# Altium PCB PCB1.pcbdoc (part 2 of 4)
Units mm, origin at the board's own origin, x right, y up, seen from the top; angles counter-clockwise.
Board outline 77.9 x 107.7 mm, 4 copper layers (Top Layer, Inner1, Inner2, Bottom Layer); 106 components, 123 nets, 650 pads, 272 vias.
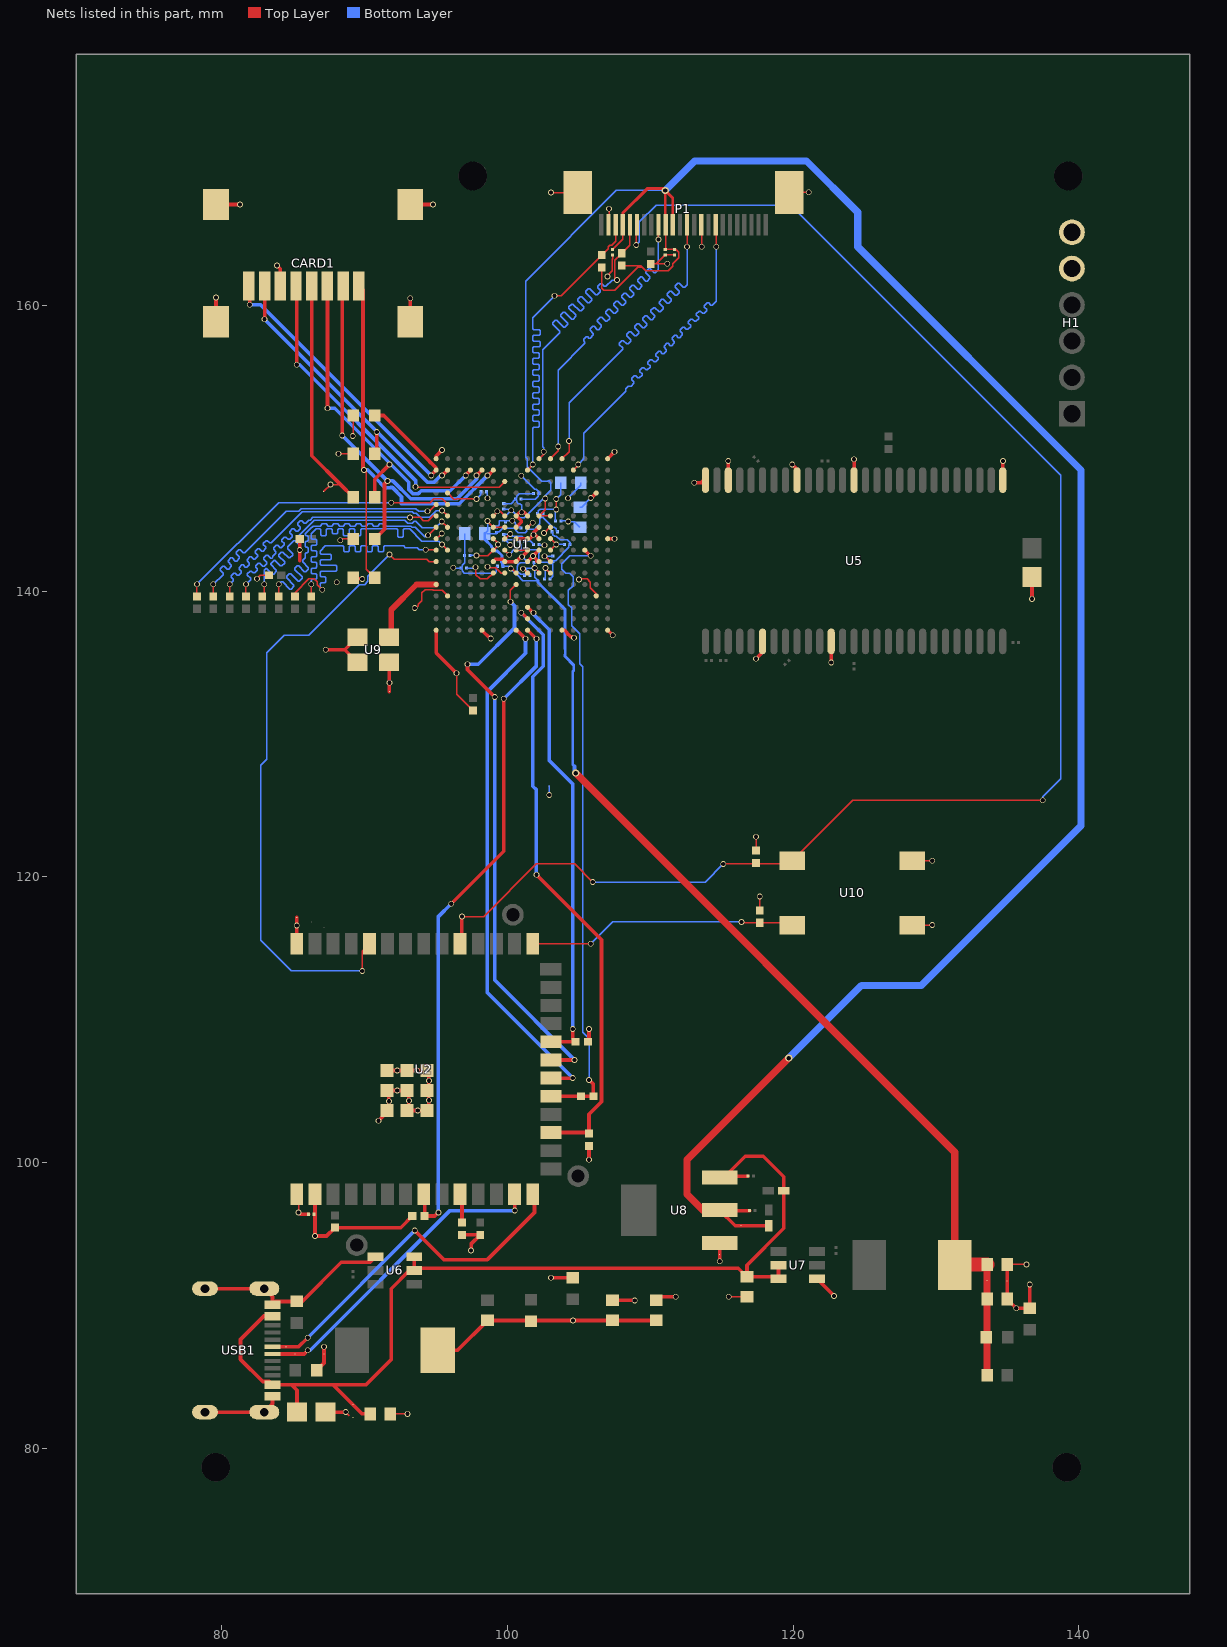
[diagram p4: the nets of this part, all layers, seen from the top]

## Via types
v1: diameter 0.4, hole 0.3, Top Layer to Bottom Layer, 269 vias
v2: diameter 0.5, hole 0.3, Top Layer to Bottom Layer, 3 vias

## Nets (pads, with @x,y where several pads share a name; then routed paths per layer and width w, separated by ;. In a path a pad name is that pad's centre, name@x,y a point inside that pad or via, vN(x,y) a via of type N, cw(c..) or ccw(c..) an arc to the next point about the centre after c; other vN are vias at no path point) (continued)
+1V1: C25.2 C27.2 C28.2 C41.1 C42.1 C43.1 C44.1 C49.1 C53.1 C54.1 C61.1 L2.2 pad.55@104.707,127.741 pad.55@133.577,91.767 R15.2 U1.G6 U1.G7 U1.L8 U1.L9 U1.L10 | length 89.6
  Top Layer w0.1: v1@98.611,144.911 98.611,144.873 U1.G6@99.024,144.46 U1.G7@99.824,144.46 ; v1(100.253,141.581) 100.303,141.581 U1.L8@100.624,141.26 ; v1(101.107,141.563) 101.121,141.563 U1.L9@101.424,141.26 ; v1(101.913,141.609) 102.224,141.298 U1.L10@102.224,141.26
  Top Layer w0.5: v2(104.79,127.258) 131.313,100.735 L2.2@131.313,92.835 ; C25.2@133.577,85.133 C28.2@133.577,90.467 pad.55@133.577,91.767 C27.2@133.577,92.88
  Top Layer w1: L2.2@131.313,92.835 131.357,92.88 C27.2@133.577,92.88
  Bottom Layer w0.1: C61.1@98.485,144.086 98.619,144.219 v1(98.619,144.903) ; C61.1@98.549,144.022 99.241,144.022 99.383,144.164 ; C41.1@99.246,144.081 99.246,144.149 99.261,144.164 99.383,144.164 ; C54.1@99.695,141.736 100.098,141.736 v1(100.253,141.581) 100.505,141.329 100.505,141.314 100.903,140.916 100.903,140.907 101.077,140.733 102.153,140.733 101.913,140.974 v1(101.913,141.609) ; C53.1@101.6,141.101 101.6,141.212 101.248,141.563 v1(101.107,141.563) 101.153,141.609 v1(101.913,141.609) ; C49.1@101.854,141.99 101.854,141.668 v1(101.913,141.609) ; C43.1@102.489,145.419 102.489,145.246 ; C44.1@103.505,144.149 103.422,144.232 103.422,144.343 103.303,144.461 103.193,144.461 102.489,145.165 102.489,145.246 ; 99.383,144.164 99.439,144.164 99.673,144.398 100.511,144.398 100.611,144.298 100.611,144.247 100.767,144.091 101.246,144.091 101.346,144.191 101.346,144.33 102.009,144.33 102.009,144.439 102.285,144.715 102.285,145.042 102.489,145.246
  Bottom Layer w0.2: C61.1@98.422,144.022 98.422,143.621 98.9,143.143 98.9,143.072 99.165,142.807 99.298,142.807 99.624,142.481 99.624,142.148 99.595,142.119 99.595,142.017 99.662,141.95 99.662,141.769 C54.1@99.695,141.736 ; 102.153,140.733 102.153,140.606 104.052,138.708 104.052,135.962 104.06,135.954 104.06,135.58 104.052,135.572 104.052,135.41 104.651,134.811 104.651,134.437 104.58,134.366 104.58,127.868 pad.55@104.707,127.741
  Bottom Layer w0.254: pad.55@104.707,127.741 104.707,127.341 v2(104.79,127.258)
+1V8: C29.1 C32.2 C34.1 C35.1 C36.1 C62.1 C63.1 P1.4 P1.10 P1.11 pad.55@116.341,95.598 R38.2 R39.2 U1.F10 U1.F11 U8.2 | length 173.3
  Top Layer w0.1: v1(102.656,146.475) 102.656,146.233 102.642,146.218 102.642,145.902 102.656,145.888 102.656,145.692 U1.F10@102.224,145.26 U1.F11@103.024,145.26 ; R38.2@106.612,162.639 106.612,162.176 106.608,162.172 106.608,161.171 106.739,161.04 107.521,161.04 109.12,162.639 109.456,162.639 ; C34.1@107.374,163.902 108.081,164.61 P1.4@108.081,165.626 ; R39.2@108.009,162.766 109.329,162.766 109.456,162.639 ; P1.10@111.081,165.626 111.081,163.927 C36.1@111.057,163.902 C35.1@111.692,163.902 111.802,163.902 112.004,163.701 112.004,163.323 111.586,162.905 111.586,162.727 111.267,162.408 109.687,162.408 109.456,162.639
  Top Layer w0.2: P1.4@108.081,165.626 108.081,166.439 109.794,168.152 110.93,168.152 v2(111.057,168.025) ; P1.10@111.081,165.626 111.057,165.651 v2(111.057,168.025) ; P1.11@111.581,165.626 111.581,167.501 v2(111.057,168.025)
  Top Layer w0.254: C29.1@116.958,96.651 114.889,96.651 115.943,95.598 pad.55@116.341,95.598 C32.2@118.296,95.598
  Top Layer w0.5: U8.2@114.861,96.68 113.695,96.68 112.581,97.794 112.581,100.207 v2(119.693,107.319)
  Bottom Layer w0.1: C63.1@99.754,145.732 100.2,145.732 v1(100.271,145.66) ; C62.1@99.881,145.233 99.881,145.269 v1(100.271,145.66) ; v2(111.057,168.025) 107.628,168.025 101.278,161.675 101.278,149.356 101.384,149.25 101.384,148.681 102.396,147.669 102.827,147.669 102.863,147.705 102.929,147.705 103.044,147.59 103.044,147.064 102.656,146.676 v1(102.656,146.475) 102.544,146.475 101.181,145.112 100.848,145.112 100.3,145.66 v1(100.271,145.66)
  Bottom Layer w0.5: v2(111.057,168.025) 113.117,170.085 120.935,170.085 124.519,166.501 124.519,164.088 140.14,148.467 140.14,123.575 128.964,112.399 124.773,112.399 v2(119.693,107.319)
+3V3: C8.2 C17.2 C19.2 C22.2 C23.2 C37.1 C39.1 C40.1 C45.1 C46.1 C47.1 C48.1 C50.1 C51.1 C52.1 C55.1 C56.1 C57.1 C58.1 C59.1 CARD1.4 H1.5 L1.2 pad.55@87.15,146.964 R3.1 R4.1 R5.2 R7.2 R11.2 R16.2 R17.2 R18.2 R19.2 R20.2 R21.2 R22.2 R23.1 U1.F6 U1.F7 U1.G9 U1.G11 U1.H6 U1.H7 U1.H11 U1.J6 U1.J7 U1.J11 U1.K11 U1.L6 U1.L7 U1.L11 U2.2 U9.1 U9.4 | length 83
  Top Layer w0.1: v1(82.484,140.858) 82.727,141.101 R23.1@83.319,141.101 ; pad.55@87.15,146.964 v1(87.637,147.451) 88.328,147.451 88.33,147.453 ; v1(88.197,149.61) R18.2@89.221,149.61 ; v1(88.324,143.556) 88.409,143.641 R17.2@89.221,143.641 ; v1@89.221,150.88 R19.2@89.221,152.277 ; v1(97.776,141.66) 97.806,141.63 97.806,141.138 98.096,140.847 98.611,140.847 U1.L6@99.024,141.26 ; v1@97.849,142.498 98.045,142.498 98.065,142.478 98.642,142.478 U1.J6@99.024,142.86 99.352,143.188 v1(99.352,143.259) 99.352,143.332 U1.H6@99.024,143.66 ; v1(98.624,141.708) 98.69,141.642 99.182,141.642 99.564,141.26 U1.L7@99.824,141.26 ; U1.F6@99.024,145.26 99.292,145.528 v1(99.292,145.578) 99.506,145.578 U1.F7@99.824,145.26 ; U1.J7@99.824,142.86 100.135,142.549 v1@100.135,142.498 ; U1.H7@99.824,143.66 99.871,143.66 v1(100.207,143.996) ; U1.G9@101.424,144.46 101.748,144.784 v1(101.786,144.784) ; v1@102.548,142.371 102.713,142.371 U1.K11@103.024,142.06 ; v1(102.576,144.06) 102.976,144.46 U1.G11@103.024,144.46 ; v1(102.675,141.609) U1.L11@103.024,141.26 ; U1.J11@103.024,142.86 103.424,143.26 v1(103.437,143.26) 103.037,143.66 U1.H11@103.024,143.66
  Top Layer w0.254: CARD1.4@86.319,161.345 86.319,149.465 88.33,147.453 R20.2@89.221,146.562 ; U2.2@86.668,97.807 86.546,97.685 v1(86.546,94.873) 87.36,94.873 R7.2@87.943,95.456 92.538,95.456 R5.2@93.352,96.27 ; v1(87.308,135.894) 88.635,135.894 ; R16.2@89.217,140.923 89.293,140.847 v1(89.848,140.847) ; U9.1@89.51,135.019 88.635,135.894 ; U9.4@89.51,136.769 88.635,135.894 ; L1.2@95.134,86.872 96.517,86.872 C19.2@98.611,88.966 101.605,88.966 R11.2@101.659,88.913 101.712,88.966 v1(104.594,88.966) C23.2@107.374,88.966 C22.2@110.422,88.966 ; R21.2@96.833,94.948 R22.2@98.103,94.948 97.468,94.313 v1(97.468,93.857) ; R3.1@105.648,108.462 105.723,108.537 v1(105.723,109.351) ; v1(105.723,100.207) R4.1@105.723,101.171 ; v1(136.711,139.45) C8.2@136.711,140.99
  Bottom Layer w0.1: C51.1@97.155,141.609 97.725,141.609 v1(97.776,141.66) ; C56.1@97.409,142.498 97.833,142.498 v1(97.841,142.49) ; C37.1@98.552,146.943 98.611,146.884 v1(98.611,146.495) ; C45.1@99.754,143.963 100.174,143.963 v1(100.207,143.996) 100.377,143.826 101.017,143.826 101.136,143.708 101.136,143.597 C46.1@101.219,143.514 101.591,143.514 C47.1@101.845,143.26 ; v1(100.135,142.539) 100.575,142.979 100.575,143.006 ; C50.1@100.965,146.435 101.964,146.435 102.152,146.622 102.152,146.733 C39.1@102.235,146.816 102.235,146.927 102.033,147.128 101.908,147.128 v1(100.976,148.06) ; v1(102.606,142.43) 103.173,142.43 C52.1@103.183,142.439 ; C48.1@102.616,140.847 102.675,140.906 v1(102.675,141.609) ; v1(103.437,143.26) C55.1@104.004,143.26 ; C40.1@103.759,144.911 104.22,144.911 v1(104.27,144.861) 104.692,144.861 C59.1@105.088,144.465 ; v1(104.248,146.483) 105.153,147.388 C58.1@105.153,147.578
  other v1: 88.07,140.607 89.188,150.847
+5V: C20.2 C26.2 C30.1 C31.2 C33.2 pad.55@89.194,83.081 U6.2 U6.3 U7.2 U7.3 U8.3 USB1.A4B9 USB1.B4A9 | length 72.1
  Top Layer w0.254: USB1.A4B9@83.574,89.272 82.977,89.272 81.339,87.634 81.339,86.238 82.884,84.693 83.353,84.693 USB1.B4A9@83.574,84.472 84.904,84.472 ; C33.2@85.292,82.554 85.292,84.084 84.904,84.472 ; C20.2@90.418,82.427 89.848,82.427 pad.55@89.194,83.081 87.803,84.472 ; U6.3@93.484,93.41 U6.2@93.484,92.46 ; U8.3@114.861,98.98 115.164,98.98 U8.3@115.248,99.064 ; C30.1@116.831,99.064 U8.3@115.248,99.064 ; U7.2@118.978,92.841 U7.3@118.978,91.891 118.852,92.017 C26.2@116.772,92.017 ; 84.904,84.472 87.803,84.472 ; 87.803,84.472 90.115,84.472 91.88,86.237 91.88,91.19 93.15,92.46 U6.2@93.484,92.46 ; U6.2@93.484,92.46 93.649,92.626 116.163,92.626 C26.2@116.772,92.017 ; U8.3@115.248,99.064 116.645,100.461 117.915,100.461 119.349,99.027 C31.2@119.349,98.048 119.349,95.407 116.772,92.83 C26.2@116.772,92.017
CCLK: R6.1 R6.2 U1.J14 U2.19 | length 44.3
  Top Layer w0.254: U2.19@103.188,104.652 R6.1@105.163,104.652 R6.2@106.029,104.652 106.029,105.489 v1(105.723,105.795) ; U1.J14@105.424,142.86 105.807,142.477 v1(105.85,142.477)
  Bottom Layer w0.1: v1(105.723,105.795) 105.723,108.674 105.269,109.128 105.269,134.697 105.067,134.899 105.067,137.001 104.51,137.557 104.51,138.813 104.282,139.042 104.282,140.041 104.601,140.36 104.601,141.014 104.365,141.249 104.08,141.249 103.795,141.533 103.795,141.901 104.371,142.477 v1(105.85,142.477)
CRYSTAL: U1.M1 U9.3 | length 5.9
  Top Layer w0.4: U9.3@91.71,136.769 91.88,136.939 91.88,138.688 93.652,140.46 U1.M1@95.024,140.46
D0: R26.1 U1.E2 | length 21
  Top Layer w0.1: R26.1@78.291,139.629 v1(78.291,140.466) ; v1@91.88,146.181 94.604,146.181 94.866,146.442 95.442,146.442 U1.E2@95.824,146.06
  Bottom Layer w0.1: v1(78.291,140.466) 84.006,146.181 v1(91.889,146.181)
D1: R27.1 U1.E1 | length 21.1
  Top Layer w0.1: R27.1@79.434,139.629 v1(79.434,140.466) ; v1(94.42,145.575) 94.539,145.575 U1.E1@95.024,146.06
  Bottom Layer w0.1: v1(79.434,140.466) 80.119,141.151 80.119,141.251 79.901,141.469 79.901,141.569 80.084,141.751 80.184,141.751 80.402,141.534 80.502,141.534 80.685,141.717 80.685,141.817 80.467,142.034 80.467,142.134 80.65,142.317 80.75,142.317 80.967,142.1 81.067,142.1 81.25,142.282 81.25,142.382 81.033,142.6 81.033,142.7 81.216,142.883 81.316,142.883 81.533,142.665 81.633,142.665 84.543,145.575 85.403,145.575 85.581,145.753 93.613,145.753 93.791,145.575 v1(94.42,145.575)
D2: R28.1 U1.F2 | length 21.5
  Top Layer w0.1: R28.1@80.577,139.629 v1(80.577,140.466) ; v1(95.433,145.63) 95.454,145.63 U1.F2@95.824,145.26
  Bottom Layer w0.1: v1(80.577,140.466) 80.831,140.72 80.831,140.82 80.677,140.974 80.677,141.074 80.86,141.257 80.96,141.257 81.114,141.103 81.214,141.103 81.396,141.286 81.396,141.386 81.242,141.54 81.242,141.64 81.425,141.823 81.525,141.823 81.679,141.669 81.779,141.669 81.962,141.851 81.962,141.951 81.808,142.105 81.808,142.205 81.991,142.388 82.091,142.388 82.245,142.234 82.345,142.234 82.528,142.417 82.528,142.517 82.374,142.671 82.374,142.771 82.557,142.954 82.657,142.954 82.811,142.8 82.911,142.8 83.094,142.983 83.094,143.083 82.94,143.237 82.94,143.337 83.122,143.52 83.222,143.52 83.376,143.366 83.476,143.366 85.664,145.553 93.361,145.553 93.471,145.444 93.639,145.444 93.91,145.173 94.586,145.173 95.043,145.63 v1(95.433,145.63)
D3: R29.1 U1.F1 | length 20.7
  Top Layer w0.1: R29.1@81.72,139.629 v1(81.72,140.466) ; v1(93.195,145.151) 93.894,145.151 94.126,144.919 94.459,144.919 94.817,145.277 95.007,145.277 U1.F1@95.024,145.26
  Bottom Layer w0.1: v1(81.72,140.466) 82.039,140.785 82.039,140.885 81.822,141.103 81.822,141.203 82.004,141.386 82.104,141.386 82.224,141.266 82.324,141.266 82.507,141.449 82.507,141.549 82.387,141.668 82.387,141.768 82.57,141.951 82.67,141.951 82.888,141.734 82.988,141.734 83.17,141.917 83.17,142.017 82.953,142.234 82.953,142.334 83.136,142.517 83.236,142.517 83.453,142.3 83.553,142.3 83.606,142.352 83.606,142.448 83.818,142.661 83.818,142.761 83.649,142.93 83.649,143.03 83.831,143.213 83.931,143.213 84.101,143.043 84.201,143.043 84.384,143.226 84.384,143.326 84.214,143.496 84.214,143.596 84.397,143.778 84.497,143.778 84.666,143.609 84.766,143.609 84.949,143.792 84.949,143.892 84.78,144.061 84.78,144.161 84.963,144.344 85.063,144.344 85.232,144.175 85.332,144.175 85.515,144.358 85.515,144.458 85.346,144.627 85.346,144.727 85.529,144.91 85.629,144.91 85.798,144.74 85.898,144.74 86.106,144.949 86.203,144.949 86.405,145.151 v1(93.195,145.151)
D4: R30.1 U1.G2 | length 21.3
  Top Layer w0.1: R30.1@82.863,139.629 82.99,139.756 v1(82.99,140.466) ; v1(95.418,144.863) 95.421,144.863 U1.G2@95.824,144.46
  Bottom Layer w0.1: v1(82.99,140.466) 82.99,141.453 83.136,141.599 83.154,141.599 83.566,141.187 83.666,141.187 83.849,141.37 83.849,141.47 83.437,141.882 83.437,141.9 83.702,142.165 83.72,142.165 84.132,141.753 84.232,141.753 84.414,141.936 84.414,142.036 84.003,142.448 84.003,142.548 84.185,142.731 84.285,142.731 84.697,142.319 84.797,142.319 84.98,142.502 84.98,142.602 84.641,142.941 84.641,143.104 85.066,143.53 85.166,143.53 85.385,143.312 85.485,143.312 85.668,143.494 85.668,143.594 85.449,143.813 85.449,143.913 86.488,144.951 92.826,144.951 93.028,144.749 93.361,144.749 93.488,144.876 93.597,144.876 94.049,144.424 94.978,144.424 v1(95.418,144.863)
D5: R31.1 U1.G1 | length 21
  Top Layer w0.1: R31.1@84.006,139.629 v1(84.006,140.466) ; v1(94.453,143.895) 94.459,143.895 U1.G1@95.024,144.46
  Bottom Layer w0.1: v1(84.006,140.466) 84.185,140.645 84.285,140.645 84.794,140.136 84.894,140.136 85.077,140.319 85.077,140.419 84.567,140.928 84.567,141.028 84.75,141.21 84.85,141.21 85.359,140.701 85.459,140.701 85.642,140.884 85.642,140.984 85.133,141.493 85.133,141.593 85.297,141.757 85.397,141.757 85.809,141.345 85.909,141.345 86.092,141.527 86.092,141.627 85.68,142.04 85.68,142.14 85.88,142.34 85.88,142.598 85.951,142.668 85.992,142.668 86.063,142.739 86.063,142.998 85.992,143.068 85.951,143.068 85.88,143.139 85.88,143.398 85.951,143.468 85.992,143.468 86.063,143.539 86.063,143.798 85.992,143.868 85.951,143.868 85.88,143.939 85.88,144.013 86.326,144.459 86.348,144.459 86.438,144.549 86.923,144.549 86.994,144.62 86.994,144.651 87.065,144.722 87.323,144.722 87.394,144.651 87.394,144.62 87.465,144.549 87.723,144.549 87.794,144.62 87.794,144.651 87.865,144.722 88.123,144.722 88.194,144.651 88.194,144.62 88.265,144.549 88.523,144.549 88.594,144.62 88.594,144.651 88.665,144.722 88.923,144.722 88.994,144.651 88.994,144.62 89.065,144.549 89.323,144.549 89.394,144.62 89.394,144.651 89.465,144.722 89.723,144.722 89.794,144.651 89.794,144.62 89.865,144.549 90.123,144.549 90.194,144.62 90.194,144.651 90.265,144.722 90.523,144.722 90.594,144.651 90.594,144.62 90.665,144.549 90.923,144.549 90.994,144.62 90.994,144.651 91.065,144.722 91.323,144.722 91.394,144.651 91.394,144.62 91.465,144.549 93.249,144.549 93.339,144.459 93.568,144.459 94.222,143.805 94.363,143.805 v1(94.453,143.895)
D6: R32.1 U1.J1 | length 20.9
  Top Layer w0.1: R32.1@85.149,139.629 85.149,139.892 86.125,140.868 86.458,140.868 86.694,140.633 86.694,140.445 v1(87.054,140.085) ; v1(94.293,142.879) 95.005,142.879 U1.J1@95.024,142.86
  Bottom Layer w0.1: v1(87.054,140.085) 86.906,140.233 86.906,140.517 86.977,140.588 87.241,140.588 87.312,140.658 87.312,140.917 87.241,140.988 86.977,140.988 86.906,141.058 86.906,141.317 86.977,141.388 87.999,141.388 88.07,141.458 88.07,141.717 87.999,141.788 86.977,141.788 86.906,141.858 86.906,142.117 86.977,142.188 87.618,142.188 87.689,142.258 87.689,142.517 87.618,142.588 86.977,142.588 86.906,142.658 86.906,142.792 87.268,143.154 88.486,143.154 88.556,143.083 88.556,142.823 88.627,142.752 88.886,142.752 88.956,142.823 88.956,143.083 89.027,143.154 89.286,143.154 89.356,143.083 89.356,142.823 89.427,142.752 89.686,142.752 89.756,142.823 89.756,143.083 89.827,143.154 90.086,143.154 90.156,143.083 90.156,142.823 90.227,142.752 90.486,142.752 90.556,142.823 90.556,143.083 90.627,143.154 90.886,143.154 90.956,143.083 90.956,142.823 91.027,142.752 91.286,142.752 91.356,142.823 91.356,143.083 91.427,143.154 92.748,143.154 92.875,143.027 93.697,143.027 93.845,142.879 v1(94.293,142.879)
D7: R34.1 U1.J2 | length 21
  Top Layer w0.1: R34.1@86.292,139.629 v1(86.292,140.466) ; v1(95.436,143.26) 95.436,143.248 U1.J2@95.824,142.86
  Bottom Layer w0.1: v1(86.292,140.466) 86.292,140.74 86.363,140.811 86.606,140.811 86.677,140.882 86.677,141.14 86.606,141.211 86.363,141.211 86.292,141.282 86.292,141.54 86.363,141.611 86.606,141.611 86.677,141.682 86.677,141.94 86.606,142.011 86.363,142.011 86.292,142.082 86.292,142.34 86.363,142.411 86.606,142.411 86.677,142.482 86.677,142.74 86.606,142.811 86.363,142.811 86.292,142.882 86.292,143.14 86.363,143.211 86.606,143.211 86.677,143.282 86.677,143.54 86.606,143.611 86.363,143.611 86.292,143.682 86.292,144.022 86.619,144.349 86.867,144.349 86.938,144.278 86.938,143.94 87.009,143.869 87.267,143.869 87.338,143.94 87.338,144.278 87.409,144.349 87.667,144.349 87.738,144.278 87.738,144.081 87.809,144.011 88.067,144.011 88.138,144.081 88.138,144.278 88.209,144.349 88.467,144.349 88.538,144.278 88.538,143.94 88.609,143.869 88.867,143.869 88.938,143.94 88.938,144.278 89.009,144.349 89.267,144.349 89.338,144.278 89.338,143.94 89.409,143.869 89.667,143.869 89.738,143.94 89.738,144.278 89.809,144.349 92.262,144.349 92.333,144.278 92.333,143.839 92.404,143.768 92.662,143.768 92.733,143.839 92.733,144.278 92.804,144.349 93.166,144.349 94.022,143.493 95.203,143.493 v1(95.436,143.26)
DIN: U1.T8 U2.20 | length 36.6
  Top Layer w0.254: U1.T8@100.624,137.26 100.674,137.26 v1(101.278,136.656) ; U2.20@103.188,105.922 v1(104.58,105.922)
  Bottom Layer w0.254: v1(101.278,136.656) 101.278,135.64 98.611,132.973 98.611,111.891 v1(104.58,105.922)
DN: pad.55@85.149,86.618 U2.13 USB1.A7 | length 22.3
  Top Layer w0.254: USB1.A7@83.574,86.622 84.87,86.622 85.788,86.622 v1(86.038,86.872) ; v1(100.516,96.651) 100.516,97.685 U2.13@100.638,97.807
  Bottom Layer w0.254: v1(86.038,86.872) 86.207,86.872 95.986,96.651 v1(100.516,96.651)
DONE: pad.55@103.761,127.315 R3.2 U1.P9 U2.22 | length 33.4
  Top Layer w0.254: U1.P9@101.424,138.86 101.794,138.49 v1(101.842,138.49) ; U2.22@103.188,108.462 R3.2@104.782,108.462 104.58,108.664 v1(104.58,109.351)
  Bottom Layer w0.254: v1(101.842,138.49) 101.842,138.378 102.929,137.291 102.929,128.147 pad.55@103.761,127.315 104.58,126.496 v1(104.58,109.351)
DOUT: U1.M8 U2.21 | length 40
  Top Layer w0.1: v1(100.224,139.245) 100.224,140.06 U1.M8@100.624,140.46
  Top Layer w0.254: v1(97.214,134.878) 97.214,134.497 v1(99.119,132.592) ; U2.21@103.188,107.192 v1(104.707,107.192)
  Bottom Layer w0.254: v1(97.214,134.878) 97.976,134.878 100.508,137.41 100.508,138.961 v1(100.224,139.245) ; v1(99.119,132.592) 99.119,112.78 v1(104.707,107.192)
DP: pad.55@84.514,87.126 U2.14 USB1.A6 | length 25.2
  Top Layer w0.254: USB1.A6@83.574,87.122 84.826,87.122 85.399,87.122 v1(86.038,87.761) ; v1(93.531,95.254) 95.563,93.222 98.611,93.222 101.908,96.519 U2.14@101.908,97.807
  Bottom Layer w0.254: v1(86.038,87.761) v1(93.531,95.254)
FSCL: P1.5 R39.1 U1.A10 | length 27
  Top Layer w0.1: U1.A10@102.224,149.26 102.548,149.584 v1(102.548,149.737) ; v1(107.671,161.759) 107.537,161.893 107.537,163.133 108.009,163.605 R39.1@108.009,163.632 108.581,164.204 P1.5@108.581,165.626
  Bottom Layer w0.1: v1(102.548,149.737) 102.548,150.023 102.467,150.103 102.467,156.894 103.656,158.083 103.656,158.183 103.184,158.655 103.184,158.755 103.367,158.938 103.467,158.938 103.939,158.466 104.039,158.466 104.222,158.649 104.222,158.749 103.75,159.221 103.75,159.321 103.933,159.504 104.033,159.504 104.505,159.032 104.605,159.032 104.788,159.215 104.788,159.315 104.315,159.787 104.315,159.887 104.498,160.07 104.598,160.07 105.07,159.597 105.17,159.597 105.353,159.78 105.353,159.88 104.931,160.302 104.931,160.402 105.114,160.585 105.214,160.585 105.636,160.163 105.736,160.163 105.919,160.346 105.919,160.446 105.497,160.868 105.497,160.968 105.68,161.151 105.78,161.151 106.202,160.729 106.302,160.729 106.508,160.934 106.508,161.034 106.318,161.224 106.318,161.324 106.5,161.507 106.6,161.507 106.79,161.317 106.89,161.317 107.332,161.759 v1(107.671,161.759)
FSDA: P1.3 R38.1 U1.B9 | length 27
  Top Layer w0.1: U1.B9@101.424,148.46 101.786,148.822 v1(101.786,148.848) ; v1(103.31,160.659) 103.766,160.659 R38.1@106.612,163.505 107.062,163.955 107.062,164.091 107.18,164.209 107.316,164.209 107.581,164.474 P1.3@107.581,165.626
  Bottom Layer w0.1: v1(101.786,148.848) 101.786,151.402 101.857,151.473 102.173,151.473 102.244,151.544 102.244,151.802 102.173,151.873 101.857,151.873 101.786,151.944 101.786,152.213 101.857,152.284 102.173,152.284 102.244,152.354 102.244,152.613 102.173,152.684 101.857,152.684 101.786,152.754 101.786,153.013 101.857,153.084 102.173,153.084 102.244,153.154 102.244,153.413 102.173,153.484 101.857,153.484 101.786,153.554 101.786,153.813 101.857,153.884 102.173,153.884 102.244,153.954 102.244,154.213 102.173,154.284 101.857,154.284 101.786,154.354 101.786,154.613 101.857,154.684 102.173,154.684 102.244,154.754 102.244,155.013 102.173,155.084 101.857,155.084 101.786,155.154 101.786,155.413 101.857,155.484 102.173,155.484 102.244,155.554 102.244,155.813 102.173,155.884 101.857,155.884 101.786,155.954 101.786,156.213 101.857,156.284 102.173,156.284 102.244,156.354 102.244,156.613 102.173,156.684 101.857,156.684 101.786,156.754 101.786,157.013 101.857,157.084 102.223,157.084 102.294,157.154 102.294,157.413 102.223,157.484 101.857,157.484 101.786,157.554 101.786,157.813 101.857,157.884 102.223,157.884 102.294,157.954 102.294,158.213 102.223,158.284 101.857,158.284 101.786,158.354 101.786,159.135 v1(103.31,160.659)
GND: C17.1 C20.1 C22.1 C23.1 C26.1 C27.1 C28.1 C33.1 C34.2 C35.2 C36.2 C37.2 C39.2 C40.2 C41.2 C42.2 C43.2 C44.2 C45.2 C46.2 C47.2 C48.2 C49.2 C50.2 C51.2 C52.2 C53.2 C54.2 C55.2 C56.2 C57.2 C58.2 C59.2 C61.2 C62.2 C63.2 CARD1.6 CARD1.9 CARD1.10 CARD1.11 CARD1.12 H1.6 P1.2 P1.15 P1.25 P1.26 pad.55@85.271,117.166 pad.55@87.181,86.618 pad.55@89.213,82.173 pad.55@91.753,132.973 pad.55@102.929,126.369 pad.55@114.861,93.568 pad.55@134.977,91.727 R9.1 R10.1 R12.1 R14.1 R24.1 R25.1 R35.2 R36.2 R37.2 U1.A1 U1.A16 U1.D2 U1.D15 U1.F8 U1.F9 U1.G8 U1.G10 U1.H1 U1.H8 U1.H9 U1.H10 U1.H16 U1.J8 U1.J9 U1.J10 U1.K6 U1.K7 U1.K8 U1.K9 U1.K10 U1.N2 U1.N15 U1.T1 U1.T5 U1.T12 U1.T16 U2.1 U2.40 U2.41 U5.6 U5.12 U5.28 U5.41 U5.46 U5.52 U5.54 U6.4 U7.4 U8.1 U9.2 U10.2 U10.4 USB1.1 USB1.2 USB1.3 USB1.4 USB1.A1B12 USB1.B1A12 | length 154.2
  Top Layer w0.1: U2.1@85.271,97.807 85.398,97.68 v1(85.398,96.524) ; v1(88.705,82.554) 88.959,82.3 ; C20.1@91.818,82.427 v1(93.023,82.427) ; v1(93.531,138.815) 93.604,138.815 93.764,138.974 93.764,139.059 94.018,139.313 94.018,139.871 94.253,140.106 94.78,140.106 94.838,140.048 95.436,140.048 U1.N2@95.824,139.66 ; 95.182,143.768 95.424,144.01 v1(95.424,144.022) ; U1.D2@95.824,146.86 96.249,146.435 96.458,146.435 96.466,146.442 97.582,146.442 97.589,146.435 v1(97.848,146.436) ; v1(96.452,134.243) 96.452,132.794 R25.1@97.595,131.651 ; U1.J8@100.624,142.86 U1.J9@101.367,142.86 ; v1(103.056,167.88) P1.26@104.926,167.88 ; v1(103.424,145.708) 103.437,145.721 v1(103.437,146.435) ; v1(105.024,140.812) 105.163,140.812 105.193,140.842 105.582,140.842 105.806,140.618 105.806,140.229 106.224,139.811 U1.N15@106.224,139.66 ; v1(107.01,162.006) 107.01,162.073 107.337,162.4 107.337,163.216 107.374,163.253 C34.2@107.374,163.512 ; P1.2@107.081,165.626 107.12,165.665 v1(107.12,166.755) ; R35.2@110.041,162.893 110.438,162.893 ; v1(111.184,162.893) 110.438,162.893 ; C35.2@111.692,163.512 C36.2@111.057,163.512 110.438,162.893 ; P1.15@113.577,165.625 113.614,165.588 113.614,164.426 113.597,164.408 v1@113.597,164.088 ; v1(115.502,90.617) C26.1@116.772,90.617 ; R36.2@117.407,121.849 v1(117.407,122.813) ; R37.2@117.661,117.658 v1(117.661,118.622) ; P1.25@119.728,167.887 121.079,167.887 v1(121.09,167.898) ; U10.4@128.338,116.626 v1(129.726,116.626) ; U10.2@128.338,121.126 v1(129.726,121.126) ; C27.1@134.977,92.88 v1(136.33,92.88)
  Top Layer w0.254: USB1.4@78.849,82.552 USB1.2@82.999,82.552 83.574,83.127 USB1.B1A12@83.574,83.672 ; USB1.3@78.849,91.192 USB1.1@82.999,91.192 83.574,90.617 USB1.A1B12@83.574,90.072 83.794,90.292 R9.1@85.276,90.292 85.657,90.292 88.393,93.029 90.108,93.029 90.118,93.039 90.413,93.039 U6.4@90.784,93.41 ; CARD1.10@79.619,158.845 v1(79.619,160.536) ; CARD1.9@79.619,167.045 v1(81.304,167.045) ; v1(83.891,162.772) 84.119,162.545 CARD1.6@84.119,161.345 ; pad.55@85.271,117.166 v1(85.271,116.594) 85.271,115.434 U2.40@85.398,115.307 ; v1(85.398,96.524) 85.525,96.397 C17.1@86.097,96.397 ; 85.478,142.117 v1(85.478,142.873) R24.1@85.478,143.641 ; R10.1@86.664,85.475 87.181,85.992 pad.55@87.181,86.618 v1(87.181,87.126) ; C33.1@87.292,82.554 v1(88.705,82.554) ; v1(90.992,102.931) 91.718,103.657 v1(91.718,104.31) 91.718,105.057 v1(92.294,105.057) 93.118,105.057 v1(93.118,104.335) 93.118,103.657 v1(93.738,103.657) 94.518,103.657 v1(94.518,104.379) v1(94.518,105.741) 94.518,106.457 v1(93.669,106.457) v1(92.294,106.457) U2.41@91.718,106.457 ; U9.2@91.71,135.019 91.753,134.976 v1(91.753,133.578) pad.55@91.753,132.973 ; CARD1.11@93.219,158.845 v1(93.219,160.494) ; CARD1.12@93.219,167.045 v1(94.801,167.045) ; U1.T1@95.024,137.26 95.024,135.671 v1(96.452,134.243) ; U1.A1@95.024,149.26 95.024,149.452 v1(95.436,149.864) ; U1.T5@98.224,137.26 98.807,136.677 v1(98.844,136.677) ; U1.K6@99.024,142.06 99.178,142.215 99.669,142.215 U1.K7@99.824,142.06 U1.K8@100.624,142.06 100.967,142.403 v1(101.037,142.403) 101.367,142.733 101.367,142.86 U1.J9@101.424,142.86 ; U1.H8@100.624,143.66 U1.H9@101.424,143.66 101.574,143.66 v1(101.843,143.928) ; U1.G8@100.624,144.46 100.976,144.812 100.976,144.908 U1.F8@100.624,145.26 100.878,145.514 v1(101.014,145.514) 101.17,145.514 U1.F9@101.424,145.26 ; U1.K9@101.424,142.06 101.802,142.439 v1(101.802,142.452) ; U1.K10@102.068,142.088 102.068,142.186 v1(101.802,142.452) ; U1.J10@102.224,142.86 102.21,142.86 v1(101.802,142.452) ; U1.H10@102.224,143.66 101.955,143.928 v1(101.843,143.928) ; U1.G10@102.224,144.46 101.843,144.079 v1(101.843,143.928) ; v1(103.056,91.943) R12.1@104.58,91.943 ; U1.T12@103.824,137.26 104.011,137.26 104.165,137.106 104.165,137.07 104.434,136.801 104.592,136.801 v1(104.665,136.728) ; v1@105.85,146.562 105.926,146.562 U1.D15@106.224,146.86 ; U1.T16@107.024,137.26 v1(107.374,136.91) ; U1.H16@107.024,143.66 v1@107.501,143.66 ; U1.A16@107.024,149.26 v1(107.501,149.737) ; C23.1@107.374,90.366 v1(108.928,90.366) ; C22.1@110.422,90.366 110.673,90.617 v1(111.793,90.617) ; v1(113.089,147.578) 113.557,147.578 U5.54@113.865,147.886 ; v1(114.861,93.105) pad.55@114.861,93.568 U8.1@114.861,94.38 ; U5.52@115.465,147.886 v1(115.465,149.102) ; v1(117.407,135.259) 117.865,135.717 U5.6@117.865,136.475 ; v1(119.947,148.848) 120.265,148.53 U5.46@120.265,147.759 ; U7.4@121.678,91.891 122.868,90.701 v1(122.868,90.682) ; v1(122.665,135.005) U5.12@122.665,136.475 ; U5.41@124.265,147.886 v1(124.265,149.229) ; U5.28@134.665,147.759 134.679,147.773 v1(134.679,149.102) ; C27.1@134.977,92.88 pad.55@134.977,91.727 C28.1@134.977,90.467 v1(135.621,89.823) R14.1@136.563,89.823 v1(136.563,91.483)
  Bottom Layer w0.1: v1@96.198,141.609 C51.2@96.765,141.609 ; C61.2@97.022,144.022 97.022,142.501 C56.2@97.019,142.498 97.019,141.974 96.848,141.803 96.848,141.692 C51.2@96.765,141.609 ; v1(97.848,146.436) 98.162,146.75 C37.2@98.162,146.943 ; C41.2@99.246,144.471 99.424,144.649 99.424,144.908 99.816,144.908 C62.2@99.881,144.843 99.945,144.908 v1(100.351,144.908) 100.451,144.908 100.574,144.785 100.574,144.725 100.809,144.489 100.869,144.489 C42.2@100.956,144.403 ; C54.2@99.305,141.736 99.246,141.677 99.246,141.355 99.149,141.258 97.005,141.258 96.848,141.415 96.848,141.526 C51.2@96.765,141.609 ; C45.2@99.754,143.573 C45.2@99.863,143.573 ; C63.2@99.754,146.122 100.262,146.122 C50.2@100.575,146.435 ; v1(100.21,143.227) C45.2@99.863,143.573 ; v1(101.014,145.514) 101.014,145.995 100.887,146.123 100.776,146.123 100.658,146.241 100.658,146.352 C50.2@100.575,146.435 ; v1(101.037,142.403) 101.05,142.403 C49.2@101.464,141.99 ; C53.2@101.21,141.101 101.15,141.161 100.94,141.161 100.705,141.396 100.705,141.73 100.737,141.761 100.737,141.83 100.897,141.99 C49.2@101.464,141.99 ; v1(101.802,142.452) 101.802,142.329 101.776,142.302 101.665,142.302 101.547,142.184 101.547,142.073 C49.2@101.464,141.99 ; C39.2@101.845,146.816 100.845,146.816 100.658,146.629 100.658,146.518 C50.2@100.575,146.435 ; C43.2@102.099,145.419 102.182,145.502 102.182,145.613 102.3,145.731 102.678,145.731 102.701,145.708 v1(103.424,145.708) 103.369,145.653 C40.2@103.369,144.911 ; C47.2@102.235,143.26 102.298,143.197 v1(102.608,143.197) ; v1(102.929,125.734) pad.55@102.929,126.369 ; C48.2@102.997,140.847 103.183,141.033 103.183,141.922 ; C44.2@103.115,144.149 103.198,144.066 103.198,143.955 103.316,143.837 103.427,143.837 103.692,143.572 104.192,143.572 104.394,143.371 C55.2@104.394,143.26 104.311,143.177 104.311,143.066 103.376,142.132 103.266,142.132 C52.2@103.183,142.049 103.183,141.922 ; v1(103.437,146.435) 103.753,146.751 C58.2@103.753,147.578 ; C59.2@105.088,145.865 105.2,145.865 v1(105.85,146.515) ; C45.2@99.863,143.573 100.77,143.573 C46.2@100.829,143.514 100.912,143.431 100.912,143.32 100.965,143.267 C57.2@100.965,142.879 102.04,142.879 102.238,142.681 102.238,142.629 102.204,142.596 102.204,142.136 102.33,142.011 102.841,142.011 102.952,141.901 103.162,141.901 103.183,141.922
  other v1: 96.213,141.624 107.501,143.662 113.614,164.088
HREF: P1.9 U1.A11 | length 27
  Top Layer w0.1: U1.A11@103.024,149.26 103.564,149.8 v1(103.564,150.118) ; v1(110.581,164.596) P1.9@110.581,165.626
  Bottom Layer w0.1: v1(103.564,150.118) 103.564,155.452 105.432,157.32 105.432,157.42 105.342,157.511 105.342,157.611 105.525,157.794 105.625,157.794 105.715,157.703 105.815,157.703 106.026,157.914 106.026,158.014 105.795,158.245 105.795,158.345 105.978,158.528 106.078,158.528 106.309,158.297 106.409,158.297 106.592,158.48 106.592,158.58 106.311,158.861 106.311,158.961 106.494,159.144 106.594,159.144 106.875,158.863 106.975,158.863 107.158,159.046 107.158,159.146 106.877,159.427 106.877,159.527 107.059,159.71 107.159,159.71 107.44,159.429 107.54,159.429 107.723,159.611 107.723,159.711 107.442,159.992 107.442,160.092 107.625,160.275 107.725,160.275 108.006,159.994 108.106,159.994 108.289,160.177 108.289,160.277 108.008,160.558 108.008,160.658 108.191,160.841 108.291,160.841 108.572,160.56 108.672,160.56 108.855,160.743 108.855,160.843 108.574,161.124 108.574,161.224 108.756,161.407 108.856,161.407 109.137,161.126 109.237,161.126 109.42,161.309 109.42,161.409 109.139,161.69 109.139,161.79 109.322,161.972 109.422,161.972 109.703,161.691 109.803,161.691 109.986,161.874 109.986,161.974 109.705,162.255 109.705,162.355 109.888,162.538 109.988,162.538 110.269,162.257 110.369,162.257 110.581,162.469 v1(110.581,164.596)
INITN: pad.55@95.182,117.225 R5.1 U1.T9 U2.8 | length 46.5
  Top Layer w0.254: U2.8@94.288,97.807 94.218,97.737 R5.1@94.218,96.27 94.928,96.27 v1(95.182,96.524) ; v1(96.071,118.114) 99.754,121.797 v1(99.754,132.465) ; U1.T9@101.424,137.26 102.028,136.656 v1(102.04,136.656)
  Bottom Layer w0.254: v1(95.182,96.524) pad.55@95.182,117.225 v1(96.071,118.114) ; v1(99.754,132.465) 102.04,134.751 v1(102.04,136.656)
M_CLK: CARD1.5 U1.C7 | length 24
  Top Layer w0.1: v1(93.586,147.296) 93.603,147.278 99.442,147.278 U1.C7@99.824,147.66
  Top Layer w0.254: CARD1.5@85.219,161.345 85.276,161.288 v1(85.276,155.833)
  Bottom Layer w0.254: v1(85.276,155.833) 85.487,155.833 93.586,147.735 v1(93.586,147.296)
M_CMD: CARD1.3 R20.1 U1.B4 | length 24.7
  Top Layer w0.254: v1(87.419,152.785) CARD1.3@87.419,161.345 ; R20.1@90.728,146.562 90.728,147.823 v1(91.753,148.848) ; v1(97.087,148.086) 97.087,148.123 U1.B4@97.424,148.46
  Bottom Layer w0.254: v1(87.419,152.785) 87.927,152.785 93.107,147.605 93.107,147.097 93.387,146.817 93.784,146.817 93.983,147.016 96.017,147.016 v1(97.087,148.086)
M_D0: CARD1.7 R18.1 U1.B2 | length 21.8
  Top Layer w0.254: v1(83.019,159.008) CARD1.7@83.019,161.345 ; R18.1@90.728,149.61 90.864,149.746 v1(90.864,151.134) ; v1(95.436,148.086) 95.45,148.086 U1.B2@95.824,148.46
  Bottom Layer w0.254: v1(83.019,159.008) 94.42,147.607 94.872,147.607 95.351,148.086 v1(95.436,148.086)
M_D1: CARD1.8 R19.1 U1.B1 | length 25.5
  Top Layer w0.254: CARD1.8@81.919,161.345 81.974,161.29 v1(81.974,160.024) ; R19.1@90.728,152.277 91.363,152.277 94.565,149.075 94.565,149.07 94.834,148.801 94.839,148.801 94.991,148.649 U1.B1@94.991,148.427 ; v1(94.674,148.086) 94.674,148.11 U1.B1@94.991,148.427 ; U1.B1@95.024,148.46 U1.B1@94.991,148.427
  Bottom Layer w0.254: v1(81.974,160.024) 82.736,160.024 v1(94.674,148.086)
M_D2: CARD1.1 R16.1 U1.B6 | length 32.2
  Top Layer w0.1: v1(89.975,148.467) 90.123,148.319 90.123,141.524 R16.1@90.724,140.923
  Top Layer w0.254: CARD1.1@89.619,161.345 89.904,161.06 89.904,148.538 v1(89.975,148.467) ; v1(98.611,148.086) 98.65,148.086 U1.B6@99.024,148.46
  Bottom Layer w0.254: v1(89.975,148.467) 90.229,148.467 91.147,147.549 91.147,147.507 91.427,147.226 91.824,147.226 91.838,147.24 91.963,147.24 92.599,146.603 92.599,146.109 96.634,146.109 v1(98.611,148.086)
M_D3: CARD1.2 R17.1 U1.B5 | length 27.5
  Top Layer w0.254: v1(88.451,150.88) 88.451,161.277 CARD1.2@88.519,161.345 ; R17.1@90.728,143.641 91.41,144.323 91.41,147.49 v1(91.626,147.705) ; v1@97.85,148.086 U1.B5@98.224,148.46
  Bottom Layer w0.254: v1(88.451,150.88) v1(91.626,147.705) 91.998,147.705 93.241,146.463 96.487,146.463 97.849,147.825 v1(97.849,148.086)
MCLK: P1.13 U1.A12 | length 27.1
  Top Layer w0.1: U1.A12@103.824,149.26 104.326,149.762 v1(104.326,150.499) ; v1(112.581,164.088) P1.13@112.581,165.626
  Bottom Layer w0.1: v1(104.326,150.499) 104.326,153.166 108.071,156.911 108.071,157.011 107.84,157.242 107.84,157.342 108.023,157.525 108.123,157.525 108.354,157.294 108.454,157.294 108.637,157.477 108.637,157.577 108.356,157.858 108.356,157.958 108.538,158.141 108.638,158.141 108.919,157.86 109.019,157.86 109.202,158.042 109.202,158.142 108.921,158.423 108.921,158.523 109.104,158.706 109.204,158.706 109.485,158.425 109.585,158.425 109.768,158.608 109.768,158.708 109.487,158.989 109.487,159.089 109.67,159.272 109.77,159.272 110.051,158.991 110.151,158.991 110.334,159.174 110.334,159.274 110.053,159.555 110.053,159.655 110.235,159.838 110.335,159.838 110.616,159.557 110.716,159.557 110.899,159.739 110.899,159.839 110.618,160.12 110.618,160.22 110.801,160.403 110.901,160.403 111.182,160.122 111.282,160.122 111.465,160.305 111.465,160.405 111.184,160.686 111.184,160.786 111.367,160.969 111.467,160.969 111.748,160.688 111.848,160.688 112.031,160.871 112.031,160.971 111.75,161.252 111.75,161.352 111.932,161.535 112.032,161.535 112.313,161.254 112.413,161.254 112.581,161.421 v1(112.581,164.088)
PCLK: P1.17 U1.B13 | length 27
  Top Layer w0.1: U1.B13@104.624,148.46 104.961,148.797 v1(104.961,148.848) ; P1.17@114.581,165.627 114.613,165.595 v1(114.613,164.088)
  Bottom Layer w0.1: v1(104.961,148.848) 105.363,149.25 105.363,151.028 108.297,153.962 108.297,154.161 108.481,154.345 108.679,154.345 108.861,154.526 108.861,154.626 108.707,154.78 108.707,154.88 108.89,155.063 108.99,155.063 109.144,154.909 109.244,154.909 109.427,155.092 109.427,155.192 109.273,155.346 109.273,155.446 109.456,155.629 109.556,155.629 109.71,155.475 109.81,155.475 109.993,155.658 109.993,155.758 109.839,155.912 109.839,156.012 110.021,156.195 110.121,156.195 110.275,156.041 110.375,156.041 110.558,156.223 110.558,156.323 110.404,156.477 110.404,156.577 110.587,156.76 110.687,156.76 110.841,156.606 110.941,156.606 111.124,156.789 111.124,156.889 110.97,157.043 110.97,157.143 111.153,157.326 111.253,157.326 111.407,157.172 111.507,157.172 111.69,157.355 111.69,157.455 111.536,157.609 111.536,157.709 111.718,157.892 111.818,157.892 111.972,157.738 112.072,157.738 112.255,157.92 112.255,158.02 112.101,158.174 112.101,158.274 112.284,158.457 112.384,158.457 112.538,158.303 112.638,158.303 112.821,158.486 112.821,158.586 112.667,158.74 112.667,158.84 112.85,159.023 112.95,159.023 113.104,158.869 113.204,158.869 113.387,159.052 113.387,159.152 113.233,159.306 113.233,159.406 113.416,159.589 113.516,159.589 113.67,159.435 113.77,159.435 113.952,159.618 113.952,159.718 113.798,159.872 113.798,159.972 113.981,160.154 114.081,160.154 114.235,160 114.335,160 114.613,160.278 v1(114.613,164.088)
PROGRAM: R37.1 U2.27 U10.3 | length 18.9
  Top Layer w0.1: U2.27@101.781,115.307 105.837,115.307 v1(105.85,115.32) ; v1(116.391,116.844) 116.443,116.792 R37.1@117.661,116.792 119.772,116.792 U10.3@119.938,116.626
  Bottom Layer w0.1: v1(105.85,115.32) 107.374,116.844 v1(116.391,116.844)
PROGRAMN: pad.55@101.786,126.348 R4.2 U1.R9 U2.17 | length 42.9
  Top Layer w0.254: v1(100.987,138.471) 101.013,138.471 U1.R9@101.424,138.06 ; v1(102.04,120.146) 106.59,115.595 106.59,104.266 105.723,103.399 R4.2@105.723,102.037 105.648,102.112 U2.17@103.188,102.112
  Bottom Layer w0.254: v1(100.987,138.471) 102.519,136.939 102.519,134.729 101.786,133.996 pad.55@101.786,126.348 102.04,126.094 v1(102.04,120.146)
RESET: P1.6 R36.1 U2.31 U10.1 | length 111.2
  Top Layer w0.1: v1(96.828,117.225) 98.357,117.225 102.04,120.908 104.707,120.908 v1(105.977,119.638) ; v1(109.025,164.215) 109.025,165.57 P1.6@109.081,165.626 ; v1(115.121,120.908) 119.72,120.908 U10.1@119.938,121.126 124.165,125.353 v1(137.473,125.353)
  Top Layer w0.254: U2.31@96.828,115.307 v1(96.828,117.225)
  Bottom Layer w0.1: v1(105.977,119.638) 113.851,119.638 v1(115.121,120.908) ; v1(109.025,164.215) 109.251,164.441 109.251,165.838 110.422,167.009 119.82,167.009 138.743,148.086 138.743,126.877 137.473,125.607 v1(137.473,125.353)
RX: U1.K1 U2.36 | length 45.5
  Top Layer w0.1: v1(89.848,113.415) 89.848,114.804 U2.36@90.351,115.307 ; v1(91.754,142.553) 92.082,142.225 94.381,142.225 94.546,142.06 U1.K1@95.024,142.06
  Bottom Layer w0.1: v1(89.848,113.415) 84.895,113.415 82.736,115.574 82.736,127.802 83.176,128.242 83.176,135.699 84.387,136.91 86.111,136.91 89.646,140.445 90.014,140.445 90.25,140.68 90.25,141.049 v1(91.754,142.553)
SCL: R21.1 U2.10 | length 1.9
  Top Layer w0.254: U2.10@96.828,97.807 96.833,97.802 R21.1@96.833,95.889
